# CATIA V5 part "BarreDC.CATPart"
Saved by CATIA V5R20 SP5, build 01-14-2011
Part number: BarreDC
Bounding box of the stored display mesh (mm): x -10 to 10, y -119.952 to 119.952, z -19.992 to 19.992
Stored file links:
  C:\Documents and Settings\ndumont\Bureau\ndumont_CAO\BarreDC.CATPart
  C:\Documents and Settings\ndumont\Bureau\ndumont_CAO\ndumont.CATProduct
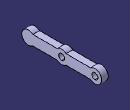
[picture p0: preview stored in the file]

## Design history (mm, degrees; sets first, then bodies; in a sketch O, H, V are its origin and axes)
External parameters (linked from other documents)
  External.DiametrePivotABetDC = 40 mm
  External.LargeurABetDC = 30 mm
  External.DiametreTrousABetDC = 18 mm
  External.EpaisseurABetDC = 20 mm
  External.EpaisseurCoulisseau = 20 mm
Set1
  Point1 to Point3: linked copy from another document
  Line1: linked copy from another document
Body1 (main body)
  Sketch1 on yz-plane, origin (0, 0, 0), H (0, 0, -1), V (0, 1, 0)
    arc A1 centre (0, -100) radius 20 from (-15, -86.7712) to (15, -86.7712) ccw
    arc A2 centre (0, 0) radius 20 from (-15, 13.2288) to (-15, -13.2288) ccw
    arc A3 centre (0, 100) radius 20 from (15, 86.7712) to (-15, 86.7712) ccw
    reference projected point E1 (0, 100) from Point2
    reference projected point E2 (0, 0) from Point3
    reference projected point E3 (0, -100) from Point1
    circle A4 centre (0, 0) radius 9
    reference projected point E4 (0, 0) from Point3
    line L1 (15, 86.7712) -> (15, 13.2288)
    line L2 (-15, 13.2288) -> (-15, 86.7712)
    line L3 (15, -13.2288) -> (15, -86.7712)
    line L4 (-15, -86.7712) -> (-15, -13.2288)
    reference projected line E5 (0, -100) -> (0, 100) from Line1
    reference projected line E6 (0, -100) -> (0, 100) from Line1
    arc A5 centre (0, 0) radius 20 from (15, -13.2288) to (15, 13.2288) ccw
    circle A6 centre (0, 100) radius 9
    point P13 (0, 100)
    reference projected point E7 (0, 100) from Point2
    radius A1 = 20 {= External.DiametrePivotABetDC /2}
    radius A2 = 20 {= External.DiametrePivotABetDC /2}
    radius A3 = 20 {= External.DiametrePivotABetDC /2}
    radius A4 = 9 {= External.DiametreTrousABetDC /2}
    distance L4 L3 = 30 {= External.LargeurABetDC}
    distance L2 L1 = 30 {= External.LargeurABetDC}
    radius A6 = 9 {= External.DiametreTrousABetDC /2}
    concentricity: A3 E1, A2 E2, A1 E3, A4 E4
    vertical: L1 V, L2 V, L3 V, L4 V
    symmetry: L4 L3 E5, L2 L1 E6
    coincidence: A2 A5, E7 P13
  Pad1: profile Sketch1, direction (1, 0, 0), length 10 {= External.EpaisseurABetDC /2}, mirrored extent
